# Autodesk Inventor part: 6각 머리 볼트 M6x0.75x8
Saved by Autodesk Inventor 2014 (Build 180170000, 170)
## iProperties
Created: 2025-10
Part Number: 6각 머리 볼트 M6x0.75x8
Material: 일반
Document SubType Name: Modeling
Designer: dg
Density: 1 g/cm^3
Appearance: 기본값
Author: dg
Author: jhkim
Description: 6각 머리 볼트 및 6각 머리 나사
Creation Date: 2025-10-01
Sending System: Autodesk Inventor 2026
Preprocessor: ST-DEVELOPER v20.1
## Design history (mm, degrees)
node "6각 머리 볼트 M6x0.75x81"
body "Solid1"
node "기준1"
